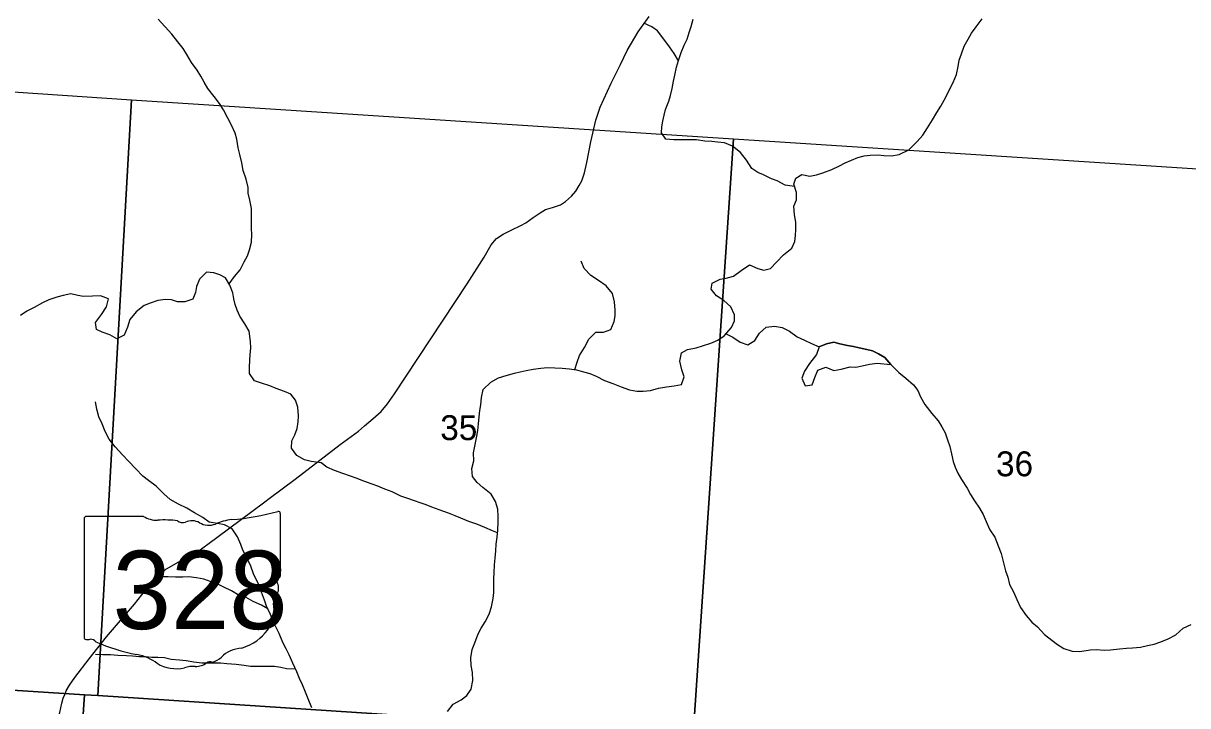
# Model space of a CAD drawing. Extents: x 0 to 34, y 0 to 22.
# Drawn here: x 24.685 to 26.642, y 19.088 to 20.236 of the extents above; entities that cross this region are included whole.
import ezdxf

# ---------------------------------------------------------------- set-up
doc = ezdxf.new("R2010")
doc.units = 0
for name, color, linetype in [('GM_X_Major_River', 7, 'Continuous'), ('GM_X_Minor_Lake', 7, 'Continuous'), ('GM_X_Minor_River', 7, 'Continuous'), ('GM_X_Section', 7, 'Continuous'), ('GM_X_Section_Text', 7, 'Continuous'), ('GM_X_State_Location', 7, 'Continuous'), ('GM_X_State_Route', 7, 'Continuous'), ('GM_X_State_Shield', 7, 'Continuous')]:
    doc.layers.add(name, color=color, linetype=linetype)

msp = doc.modelspace()

# ---------------------------------------------------------------- linework, layer by layer
at = {"layer": 'GM_X_Major_River'}
for points in [[(25.8503, 19.7779), (25.8413, 19.789), (25.8429, 19.7992), (25.8566, 19.8059), (25.8665, 19.8077), (25.879, 19.8111), (25.892, 19.8204), (25.9057, 19.8302), (25.9201, 19.824), (25.9299, 19.8209), (25.9409, 19.8235), (25.9512, 19.8344), (25.9631, 19.8468), (25.9768, 19.8581), (25.9818, 19.8691), (25.983, 19.8793), (25.9835, 19.8896), (25.9839, 19.9017), (25.9813, 19.9142), (25.9803, 19.9287), (25.9849, 19.9392), (25.9846, 19.9518), (25.9802, 19.9658), (25.984, 19.9757), (25.9939, 19.9817), (26.0072, 19.9789), (26.0186, 19.9815), (26.0292, 19.9848), (26.0441, 19.9904), (26.057, 19.9964), (26.0669, 20.0016), (26.0775, 20.0061), (26.0882, 20.0102), (26.0988, 20.0131), (26.1087, 20.0146), (26.122, 20.0149), (26.1318, 20.014), (26.1447, 20.0135), (26.1576, 20.0157), (26.1736, 20.0232), (26.1874, 20.0375), (26.1969, 20.0481), (26.205, 20.0605), (26.2134, 20.0737), (26.2207, 20.0862), (26.2276, 20.0968), (26.236, 20.1119), (26.2414, 20.1236), (26.2483, 20.1368), (26.2537, 20.1501), (26.2565, 20.1637), (26.2581, 20.1739), (26.2619, 20.1849), (26.2666, 20.1978), (26.2731, 20.2095), (26.2792, 20.2193), (26.2869, 20.2302), (26.2968, 20.2438)], [(25.3981, 19.0787), (25.4077, 19.0908), (25.421, 19.0982), (25.4309, 19.1058), (25.4378, 19.116), (25.4409, 19.1307), (25.4403, 19.144), (25.4381, 19.1558), (25.4374, 19.1687), (25.4398, 19.1827), (25.444, 19.1944), (25.4498, 19.2092), (25.4548, 19.219), (25.4613, 19.2292), (25.4682, 19.2424), (25.4721, 19.2549), (25.4752, 19.2686), (25.4761, 19.2788), (25.4762, 19.3023), (25.4767, 19.3118), (25.4775, 19.3254), (25.4783, 19.3364), (25.4796, 19.3489), (25.48, 19.3599), (25.4816, 19.3717), (25.4828, 19.3838), (25.4833, 19.3975), (25.4834, 19.4069), (25.4827, 19.4187), (25.479, 19.4316), (25.4715, 19.4442), (25.4579, 19.4553), (25.4481, 19.4637), (25.4402, 19.4737), (25.4391, 19.4873), (25.4423, 19.5002), (25.442, 19.5138), (25.4447, 19.5275), (25.4475, 19.5419), (25.4494, 19.5513), (25.4506, 19.5623), (25.4515, 19.5745), (25.4527, 19.5847), (25.4543, 19.5942), (25.4555, 19.6067), (25.4582, 19.6203), (25.4712, 19.6327), (25.4841, 19.6399), (25.4971, 19.6439), (25.5107, 19.6476), (25.5202, 19.6498), (25.5305, 19.652), (25.5423, 19.6542), (25.5552, 19.6564), (25.5662, 19.6571), (25.5912, 19.6561), (25.6033, 19.6549), (25.6151, 19.6533), (25.6268, 19.6502), (25.6374, 19.6471), (25.6484, 19.6424), (25.6624, 19.6355), (25.6764, 19.6305), (25.6904, 19.6247), (25.7044, 19.6196), (25.7165, 19.6173), (25.7271, 19.6172), (25.7393, 19.6183), (25.753, 19.6223), (25.7663, 19.6249), (25.7792, 19.6263), (25.7913, 19.6289), (25.7963, 19.6417), (25.7922, 19.6535), (25.7885, 19.668), (25.7917, 19.682), (25.8019, 19.6876), (25.8164, 19.6905), (25.827, 19.6938), (25.8411, 19.6983), (25.8525, 19.7031), (25.8632, 19.7103), (25.8758, 19.7246), (25.8804, 19.7356), (25.8805, 19.7458), (25.8745, 19.7591), (25.8628, 19.7698), (25.8503, 19.7779)]]:
    msp.add_lwpolyline(points, dxfattribs=at)
at = {"layer": 'GM_X_Minor_Lake'}
for points in [[(26.0229, 19.6918), (26.0184, 19.6793), (26.0067, 19.6641), (25.9984, 19.6512), (25.9939, 19.6391), (25.9996, 19.6262), (26.0109, 19.6281), (26.0158, 19.6402), (26.0207, 19.6528), (26.0339, 19.6577), (26.0476, 19.6521), (26.0601, 19.6544), (26.0748, 19.6582), (26.0847, 19.6579), (26.0953, 19.6598), (26.1074, 19.6628), (26.1202, 19.6644), (26.1433, 19.6622)], [(26.1433, 19.6622), (26.1331, 19.6739), (26.1224, 19.6803), (26.1126, 19.6852), (26.1031, 19.6878), (26.0899, 19.6901), (26.0804, 19.6923), (26.0705, 19.6942), (26.0577, 19.6972), (26.0478, 19.6998), (26.0353, 19.6968), (26.0229, 19.6918)]]:
    msp.add_lwpolyline(points, dxfattribs=at)
at = {"layer": 'GM_X_Minor_River'}
for points in [[(25.0315, 19.7978), (25.0405, 19.8103), (25.0496, 19.8217), (25.0567, 19.835), (25.062, 19.8449), (25.0654, 19.8551), (25.0691, 19.868), (25.0695, 19.8809), (25.069, 19.8908), (25.069, 19.9006), (25.0686, 19.9132), (25.0686, 19.9245), (25.0659, 19.9385), (25.0635, 19.9507), (25.0631, 19.9601), (25.0597, 19.9742), (25.0551, 19.9886), (25.0528, 20.0014), (25.0493, 20.0155), (25.0466, 20.0265), (25.044, 20.0412), (25.0413, 20.0515), (25.0352, 20.0651), (25.0291, 20.0768), (25.0218, 20.0905), (25.015, 20.1011), (25.0059, 20.1132), (24.9956, 20.1264), (24.9891, 20.1374), (24.9838, 20.1472), (24.9773, 20.1571), (24.9678, 20.1703), (24.9602, 20.1836), (24.9537, 20.1938), (24.945, 20.2048), (24.9347, 20.218), (24.9119, 20.243)], [(25.9815, 19.9616), (25.9656, 19.9639), (25.9523, 19.9714), (25.9428, 19.9748), (25.9292, 19.9812), (25.9197, 19.985), (25.9098, 19.9922), (25.9007, 20.0058), (25.8908, 20.0187), (25.8775, 20.0296), (25.8639, 20.0353), (25.8522, 20.036), (25.8423, 20.0371), (25.831, 20.0378), (25.8169, 20.0401), (25.8056, 20.0404), (25.792, 20.04), (25.7787, 20.04), (25.7655, 20.0411), (25.7579, 20.0521), (25.7586, 20.0619), (25.7601, 20.0714), (25.7623, 20.0817), (25.7645, 20.0911), (25.7702, 20.1052), (25.7728, 20.1147), (25.7758, 20.1264), (25.778, 20.1389), (25.7806, 20.1492), (25.7832, 20.1625), (25.7866, 20.1738), (25.7911, 20.1871), (25.796, 20.1993), (25.8013, 20.2095), (25.8046, 20.2205), (25.8076, 20.2308), (25.8114, 20.2429)], [(25.7864, 20.1731), (25.779, 20.1852), (25.7714, 20.1965), (25.7619, 20.2094), (25.7512, 20.2234), (25.7418, 20.2302), (25.7285, 20.2363)], [(25.6121, 19.6537), (25.616, 19.6662), (25.6201, 19.6772), (25.6284, 19.6909), (25.6359, 19.7049), (25.6473, 19.7167), (25.6605, 19.7167), (25.673, 19.7213), (25.6782, 19.7346), (25.6801, 19.7441), (25.6801, 19.7535), (25.6789, 19.7679), (25.6754, 19.7816), (25.6652, 19.7944), (25.6519, 19.8035), (25.639, 19.8122), (25.628, 19.8239), (25.623, 19.836)], [(25.4824, 19.3791), (25.4738, 19.3826), (25.4609, 19.3883), (25.4473, 19.3936), (25.434, 19.3985), (25.4204, 19.4041), (25.4109, 19.4079), (25.3999, 19.412), (25.384, 19.4181), (25.3722, 19.4222), (25.3624, 19.4263), (25.3522, 19.4297), (25.3427, 19.4331), (25.3317, 19.4369), (25.32, 19.4406), (25.3055, 19.4482), (25.2927, 19.4527), (25.2809, 19.4576), (25.2714, 19.461), (25.2578, 19.4663), (25.2445, 19.4712), (25.2351, 19.4742), (25.2222, 19.4791), (25.2085, 19.484), (25.1956, 19.4896), (25.1861, 19.4968), (25.1691, 19.499), (25.1577, 19.5017), (25.1448, 19.5092), (25.1361, 19.5217), (25.1364, 19.5338), (25.1417, 19.5441), (25.1455, 19.5547), (25.1473, 19.5661), (25.148, 19.5759), (25.1465, 19.5903), (25.1427, 19.6021), (25.1347, 19.6123), (25.1244, 19.6168), (25.1104, 19.6217), (25.0994, 19.6262), (25.0858, 19.6308), (25.0737, 19.6349), (25.0653, 19.647), (25.0653, 19.6576), (25.0663, 19.6694), (25.0667, 19.6792), (25.0678, 19.6895), (25.0674, 19.7009), (25.0647, 19.7183), (25.0574, 19.7308), (25.0491, 19.7436), (25.0445, 19.7535), (25.0414, 19.763), (25.0391, 19.7728), (25.0372, 19.783), (25.0326, 19.7959), (25.0254, 19.808), (25.0155, 19.8133), (25.0057, 19.8167), (24.9932, 19.8178), (24.9815, 19.806), (24.9766, 19.7935), (24.9747, 19.7836), (24.9702, 19.7719), (24.9566, 19.7677), (24.9445, 19.7677), (24.9343, 19.771), (24.9241, 19.7718), (24.9116, 19.7702), (24.8983, 19.7656), (24.8885, 19.7618), (24.8749, 19.7508), (24.8644, 19.7379), (24.8602, 19.725), (24.8546, 19.7117), (24.8425, 19.7052), (24.8308, 19.712), (24.8179, 19.7165), (24.8084, 19.7214), (24.8068, 19.7328), (24.8166, 19.7465), (24.8249, 19.7594), (24.8283, 19.7727), (24.815, 19.7776), (24.8018, 19.7772), (24.7866, 19.7764), (24.7772, 19.7782), (24.765, 19.7809), (24.7522, 19.7786), (24.7416, 19.7755), (24.7284, 19.7713), (24.7174, 19.766), (24.7034, 19.758), (24.6913, 19.7519), (24.6804, 19.7446)], [(25.8665, 19.714), (25.8778, 19.7081), (25.8903, 19.6998), (25.9032, 19.6953), (25.9149, 19.7025), (25.9225, 19.7151), (25.9338, 19.725), (25.9478, 19.7269), (25.9607, 19.7243), (25.9728, 19.7182), (25.9857, 19.7088), (25.9982, 19.7031), (26.0103, 19.6975), (26.0229, 19.6918), (26.0353, 19.6968), (26.0478, 19.6998), (26.0577, 19.6972), (26.0705, 19.6942), (26.0804, 19.6923), (26.0899, 19.6901), (26.1031, 19.6878), (26.1126, 19.6852), (26.1224, 19.6803), (26.1331, 19.6739), (26.1433, 19.6622), (26.1566, 19.6489), (26.1684, 19.6391), (26.1813, 19.6281), (26.1885, 19.6183), (26.1931, 19.6081), (26.2007, 19.5948), (26.2121, 19.5801), (26.2231, 19.5676), (26.2292, 19.5574), (26.2349, 19.5471), (26.2384, 19.5358), (26.2426, 19.5244), (26.2456, 19.5123), (26.2483, 19.499), (26.2518, 19.4896), (26.256, 19.4793), (26.2621, 19.4691), (26.2716, 19.4544), (26.2773, 19.4434), (26.2841, 19.4332), (26.2925, 19.4207), (26.2986, 19.4101), (26.3054, 19.3945), (26.31, 19.3843), (26.318, 19.3718), (26.3237, 19.3574), (26.3287, 19.3446), (26.3325, 19.3286), (26.336, 19.315), (26.3398, 19.3044), (26.3429, 19.2923), (26.3497, 19.2798), (26.3551, 19.2669), (26.3615, 19.2537), (26.3707, 19.24), (26.3802, 19.2291), (26.3897, 19.2211), (26.4014, 19.2083), (26.414, 19.1984), (26.4238, 19.1916), (26.4344, 19.1848), (26.4481, 19.1803), (26.461, 19.1796), (26.4784, 19.1823), (26.4886, 19.1827), (26.5026, 19.1816), (26.5124, 19.1824), (26.5279, 19.1839), (26.5393, 19.1851), (26.5495, 19.1859), (26.5628, 19.187), (26.5749, 19.1894), (26.5858, 19.192), (26.5972, 19.1959), (26.6097, 19.2008), (26.6225, 19.2077), (26.6346, 19.2187), (26.6482, 19.2248)], [(25.1704, 19.085), (25.1643, 19.0998), (25.1594, 19.1112), (25.1544, 19.1237), (25.1495, 19.1339), (25.1449, 19.1456), (25.1384, 19.16), (25.1323, 19.1737), (25.1273, 19.1843), (25.1213, 19.1945), (25.1151, 19.2096), (25.1075, 19.2255), (25.101, 19.2418), (25.0938, 19.2558), (25.0904, 19.2657), (25.0854, 19.2793), (25.0827, 19.2888), (25.077, 19.2998), (25.0724, 19.31), (25.0675, 19.3229), (25.0617, 19.3361), (25.0545, 19.3498), (25.0511, 19.3596), (25.0453, 19.3725), (25.0362, 19.3857), (25.0237, 19.3929), (25.0116, 19.3948), (24.9976, 19.397), (24.9869, 19.4049), (24.9729, 19.4129), (24.96, 19.4204), (24.946, 19.4272), (24.9323, 19.4351), (24.9213, 19.445), (24.9084, 19.4578), (24.8955, 19.4673), (24.886, 19.4745), (24.8743, 19.4866), (24.8621, 19.4998), (24.8526, 19.5096), (24.8397, 19.524), (24.8294, 19.5369), (24.823, 19.5494), (24.8176, 19.5626), (24.8123, 19.5744), (24.8088, 19.5869), (24.8069, 19.5997)], [(25.0961, 19.2515), (25.0855, 19.2573), (25.0718, 19.2634), (25.0601, 19.2702), (25.0483, 19.2739), (25.035, 19.2815), (25.0225, 19.2879), (25.0112, 19.2935), (25.0013, 19.2966), (24.9888, 19.3011), (24.9763, 19.3033), (24.9634, 19.3052), (24.9532, 19.3048), (24.9411, 19.3044), (24.9286, 19.3051), (24.9169, 19.3054)], [(25.143, 19.1498), (25.1278, 19.1505), (25.118, 19.1528), (25.1074, 19.1543), (25.0949, 19.1546), (25.0843, 19.1542), (25.0672, 19.1545), (25.0563, 19.156), (25.043, 19.1575), (25.0271, 19.159), (25.0169, 19.1597), (24.9851, 19.1597), (24.9718, 19.1615), (24.959, 19.1638), (24.948, 19.1649), (24.9336, 19.1664), (24.9226, 19.169), (24.9112, 19.1697), (24.9014, 19.1693), (24.8904, 19.1704), (24.8798, 19.1708), (24.8688, 19.1715), (24.8586, 19.1722), (24.8439, 19.173), (24.8317, 19.1741), (24.8189, 19.1737), (24.8067, 19.1748)]]:
    msp.add_lwpolyline(points, dxfattribs=at)
at = {"layer": 'GM_X_Section'}
for points in [[(24.8672, 20.1076), (24.8107, 19.1055), (24.788, 19.1066), (23.7939, 19.171), (23.856, 20.1758)], [(25.8788, 20.042), (25.8109, 19.0399), (25.7909, 19.041), (24.8107, 19.1055), (24.8672, 20.1076)], [(25.8788, 20.042), (26.893, 19.9764), (26.8274, 18.9732), (25.8109, 19.0399)], [(23.7643, 19.174), (23.7939, 19.171), (24.788, 19.1066), (24.7175, 18.0761), (23.7006, 18.1492)], [(24.788, 19.1066), (24.8107, 19.1055), (25.7909, 19.041), (25.7287, 17.9991), (24.7175, 18.0761)]]:
    msp.add_lwpolyline(points, close=True, dxfattribs=at)
at = {"layer": 'GM_X_State_Route'}
for points in [[(25.2587, 19.5589), (25.2736, 19.5712), (25.2869, 19.5835), (25.2972, 19.596), (25.3094, 19.613), (25.3288, 19.6429), (25.4314, 19.7979), (25.4599, 19.843), (25.4716, 19.8635), (25.4808, 19.8741), (25.4916, 19.8817), (25.505, 19.8881), (25.5215, 19.8959), (25.53, 19.9005), (25.5425, 19.9095), (25.554, 19.9176), (25.5632, 19.9228), (25.5747, 19.9265), (25.588, 19.9307), (25.5965, 19.9362), (25.6066, 19.9454), (25.6138, 19.9541), (25.6198, 19.9633), (25.6239, 19.9714), (25.6283, 19.9847), (25.6322, 20.002), (25.6391, 20.0367), (25.6478, 20.0735), (25.655, 20.0951), (25.6736, 20.1352), (25.6888, 20.1667), (25.7002, 20.1904), (25.7189, 20.2216), (25.7373, 20.2477)], [(25.0986, 19.4369), (25.1424, 19.4694), (25.2176, 19.5276), (25.2484, 19.5504), (25.2587, 19.5589)], [(24.7196, 18.9831), (24.7288, 19.0119), (24.7465, 19.0772), (24.75, 19.0924), (24.7525, 19.1011), (24.755, 19.1075), (24.7573, 19.1133), (24.7631, 19.1232), (24.7718, 19.1361), (24.796, 19.1672), (24.8254, 19.2044), (24.8724, 19.2592), (24.897, 19.2907), (24.9066, 19.3027), (24.9232, 19.3171), (24.9455, 19.33), (24.9742, 19.3445), (25.0104, 19.3714), (25.0913, 19.4315), (25.0986, 19.4369)]]:
    msp.add_lwpolyline(points, dxfattribs=at)
at = {"layer": 'GM_X_State_Shield'}
for p, q in [((24.7877, 19.4033), (24.7877, 19.2032)), ((24.8874, 19.4068), (24.7909, 19.4068)), ((25.1173, 19.307), (25.1173, 19.4117)), ((25.1172, 19.3071), (25.1173, 19.307))]:
    msp.add_line(p, q, dxfattribs=at)
for centre, major_axis, start_param, end_param in [((24.9999, 19.6796), (0.3495, 0), 4.814394, 5.042369), ((25.1136, 19.4122), (0.00367, 0), 6.141152, 7.989035), ((24.7915, 19.4038), (0.00382, 0), 1.712693, 3.28349), ((24.9104, 19.43), (0.037, 0), 4.042523, 4.731795), ((24.9227, 19.2944), (0.133, 0), 1.404758, 1.657858), ((24.9529, 19.4048), (0.0107, 0), 3.836095, 5.185415), ((24.9686, 19.3817), (0.0222, 0), 0.950623, 2.079405), ((24.9973, 19.4134), (0.0267, 0), 4.081561, 5.145723), ((25.0444, 19.3456), (0.0703, 0), 1.699011, 2.107814), ((25.1164, 19.2994), (0.00568, 0), 1.883978, 3.671073), ((25.1134, 19.3066), (0.00393, 0), 5.05454, 6.418171), ((25.0803, 19.2861), (0.0341, 0), 5.934695, 6.695948), ((25.0194, 19.2499), (0.0874, 0), 5.101752, 6.440018), ((25.1304, 19.2632), (0.0248, 0), 2.387724, 3.262537), ((24.7915, 19.2028), (0.00385, 0), 3.00124, 4.508301), ((24.7921, 19.2232), (0.0294, 0), 4.665946, 4.897461), ((24.7981, 19.1917), (0.0106, 0), 0.519207, 1.627899), ((24.9319, 19.3715), (0.2524, 0), 4.195997, 4.488961), ((25.0563, 19.147), (0.0479, 0), 1.647645, 2.488434), ((24.8567, 19.1133), (0.079, 0), 0.823519, 1.323587), ((24.9747, 19.1757), (0.0267, 0), 4.691044, 5.507374), ((24.9988, 19.1563), (0.00752, 0), 1.147584, 2.315152), ((24.9956, 19.1838), (0.0282, 0), 4.937069, 5.64225), ((24.9421, 19.1907), (0.0501, 0), 4.026481, 4.996735), ((24.971, 19.1215), (0.0412, 0), 1.495662, 1.94098)]:
    msp.add_ellipse(centre, major_axis=major_axis, ratio=0.8, start_param=start_param, end_param=end_param, dxfattribs=at)

# ---------------------------------------------------------------- texts
at = {"layer": 'GM_X_Section_Text'}
for s, p in [('35', (25.3861, 19.5351)), ('36', (26.3202, 19.4743))]:
    msp.add_text(s, height=0.04186, rotation=0, dxfattribs=at).set_placement(p)
at = {"layer": 'GM_X_State_Location'}
for s in ['s', 'r']:
    msp.add_text(s, height=0.000189, dxfattribs=at).set_placement((24.9488, 19.29))
msp.add_text('328', height=0.000189, rotation=0, dxfattribs=at).set_placement((24.8819, 19.2762))
at = {"layer": 'GM_X_State_Shield'}
msp.add_text('328', height=0.13184, dxfattribs=at).set_placement((24.8353, 19.2173))

doc.saveas('drawing.dxf')
